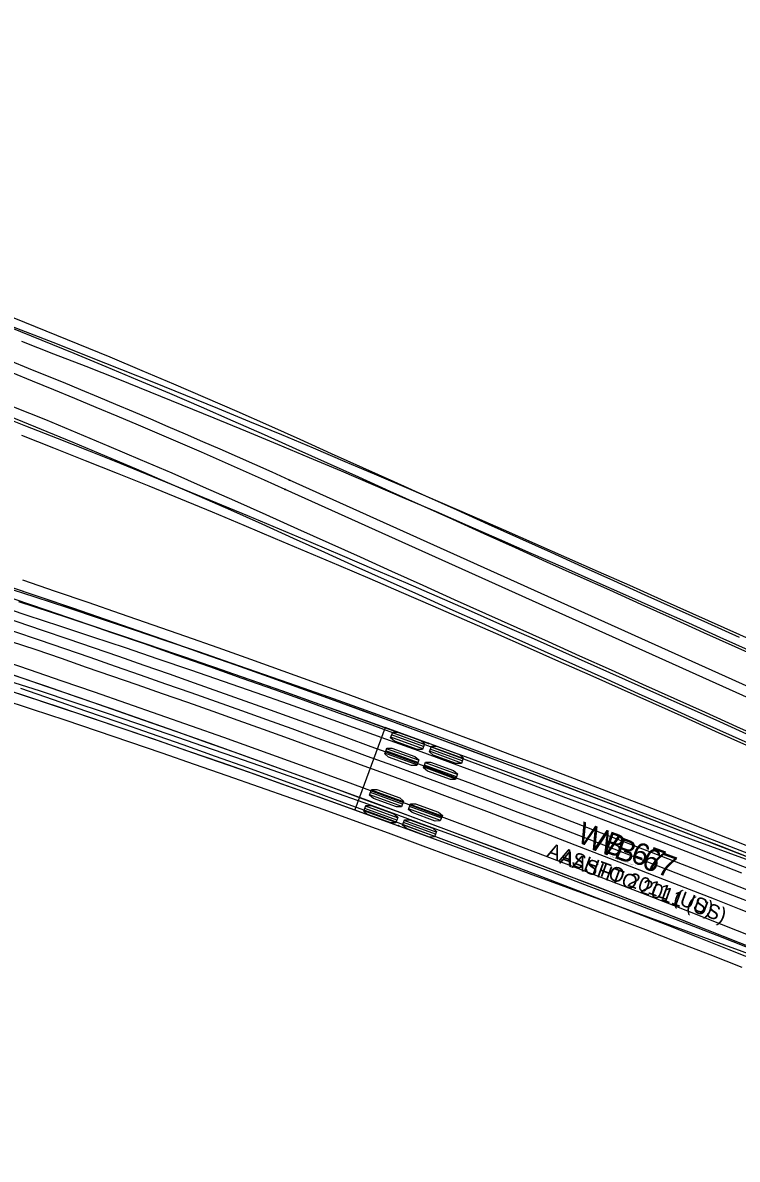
# Model space of a CAD drawing. Extents: x 916040 to 917457, y 328936 to 330267.
# Drawn here: x 916963.2 to 917032.5, y 329557.9 to 329668.1 of the extents above; entities that cross this region are included whole.
import ezdxf

# ---------------------------------------------------------------- set-up
doc = ezdxf.new("R2010")
doc.units = 0
for name, color, linetype in [('EB_Thru_WB67', 7, 'Continuous'), ('EB_Thru_WB67_v2', 7, 'Continuous'), ('NB_RightontoRoute25_WB67', 7, 'Continuous'), ('NB_ThruontoManchester_WB67', 7, 'Continuous'), ('SB_LeftontoRoute25_WB67', 7, 'Continuous'), ('WB_LeftontoSaco_WB67', 7, 'Continuous'), ('WB_RightontoManchester_WB67', 7, 'Continuous'), ('WB_Thru_WB67', 7, 'Continuous')]:
    doc.layers.add(name, color=color, linetype=linetype)

msp = doc.modelspace()

# ---------------------------------------------------------------- linework, layer by layer
at = {"layer": 'EB_Thru_WB67'}
for p, q in [((916998.31, 329599.77), (916995.39, 329591.79)), ((917048.09, 329581.6), (916998.31, 329599.77)), ((917002.13, 329598.14), (916999.03, 329599.27)), ((917001.97, 329597.71), (916998.87, 329598.84)), ((917002.05, 329597.92), (916998.95, 329599.05)), ((917001.4, 329596.16), (916998.3, 329597.29)), ((917001.48, 329596.37), (916998.38, 329597.5)), ((917001.56, 329596.59), (916998.46, 329597.72)), ((917005.73, 329596.33), (917002.63, 329597.47)), ((917005.8, 329596.55), (917002.7, 329597.68)), ((917005.88, 329596.76), (917002.78, 329597.9)), ((917005.16, 329594.78), (917002.06, 329595.92)), ((917005.24, 329595), (917002.14, 329596.13)), ((917005.32, 329595.21), (917002.22, 329596.35)), ((916999.93, 329592.13), (916996.83, 329593.26)), ((917000.01, 329592.35), (916996.91, 329593.48)), ((917000.09, 329592.56), (916996.99, 329593.69)), ((916995.39, 329591.79), (917045.18, 329573.62)), ((916999.37, 329590.58), (916996.27, 329591.71)), ((916999.45, 329590.8), (916996.35, 329591.93)), ((916999.53, 329591.01), (916996.43, 329592.14)), ((917003.69, 329590.76), (917000.59, 329591.89)), ((917003.77, 329590.98), (917000.67, 329592.11)), ((917003.85, 329591.19), (917000.75, 329592.32)), ((917003.2, 329589.43), (917000.1, 329590.56)), ((917003.28, 329589.64), (917000.18, 329590.77)), ((917003.13, 329589.21), (917000.03, 329590.34))]:
    msp.add_line(p, q, dxfattribs=at)
for points in [[(916961.68, 329613.51), (916964.85, 329612.44), (916968.01, 329611.36), (916971.18, 329610.27), (916974.34, 329609.17), (916977.5, 329608.07), (916980.66, 329606.96), (916983.82, 329605.84), (916986.97, 329604.72), (916990.12, 329603.59), (916993.27, 329602.45), (916996.42, 329601.31), (916999.56, 329600.15), (917002.7, 329599), (917005.84, 329597.83), (917008.97, 329596.66), (917012.11, 329595.48), (917015.24, 329594.29), (917018.36, 329593.1), (917021.49, 329591.9), (917024.61, 329590.69), (917027.73, 329589.48), (917030.85, 329588.26), (917033.96, 329587.03)], [(916963, 329611.92), (916966.18, 329610.88), (916969.36, 329609.83), (916972.53, 329608.76), (916975.7, 329607.69), (916978.87, 329606.61), (916982.03, 329605.52), (916985.2, 329604.42), (916988.36, 329603.31), (916991.51, 329602.2), (916994.66, 329601.08), (916997.81, 329599.94), (917000.96, 329598.8), (917002.53, 329598.23)], [(916962.36, 329604.83), (916965.51, 329603.76), (916968.65, 329602.68), (916971.8, 329601.59), (916974.94, 329600.49), (916978.08, 329599.39), (916981.22, 329598.27), (916984.36, 329597.16), (916987.49, 329596.03), (916990.62, 329594.9), (916993.75, 329593.76), (916996.88, 329592.62), (917000, 329591.46), (917003.12, 329590.31), (917006.24, 329589.14), (917009.36, 329587.97), (917012.47, 329586.79), (917015.58, 329585.6), (917018.69, 329584.41), (917021.79, 329583.2), (917024.9, 329582), (917028, 329580.78), (917031.09, 329579.56), (917034.19, 329578.33)], [(916960.36, 329603.84), (916963.52, 329602.81), (916966.67, 329601.76), (916969.82, 329600.71), (916972.97, 329599.64), (916976.11, 329598.57), (916979.26, 329597.49), (916982.4, 329596.4), (916985.53, 329595.3), (916988.67, 329594.19), (916991.8, 329593.07), (916994.93, 329591.95), (916998.06, 329590.82), (916999.62, 329590.25)]]:
    msp.add_lwpolyline(points, dxfattribs=at)
for points in [[(917002.14, 329598.19), (917001.95, 329597.65), (917001.46, 329597.65), (916999.22, 329598.46), (916998.85, 329598.78), (916999.05, 329599.32), (916999.54, 329599.32), (917001.77, 329598.51)], [(917001.58, 329596.64), (917001.38, 329596.1), (917000.89, 329596.1), (916998.66, 329596.91), (916998.28, 329597.23), (916998.48, 329597.77), (916998.97, 329597.77), (917001.2, 329596.96)], [(917005.9, 329596.82), (917005.71, 329596.28), (917005.21, 329596.28), (917002.98, 329597.09), (917002.61, 329597.41), (917002.8, 329597.95), (917003.3, 329597.95), (917005.53, 329597.14)], [(917005.34, 329595.27), (917005.14, 329594.73), (917004.65, 329594.73), (917002.42, 329595.54), (917002.04, 329595.86), (917002.24, 329596.4), (917002.73, 329596.4), (917004.96, 329595.59)], [(917000.11, 329592.62), (916999.91, 329592.08), (916999.42, 329592.07), (916997.19, 329592.89), (916996.81, 329593.21), (916997.01, 329593.75), (916997.5, 329593.75), (916999.74, 329592.94)], [(916999.54, 329591.07), (916999.35, 329590.53), (916998.86, 329590.52), (916996.62, 329591.34), (916996.25, 329591.66), (916996.44, 329592.2), (916996.94, 329592.2), (916999.17, 329591.39)], [(917003.87, 329591.24), (917003.67, 329590.71), (917003.18, 329590.7), (917000.95, 329591.52), (917000.57, 329591.84), (917000.77, 329592.38), (917001.26, 329592.38), (917003.49, 329591.56)], [(917003.3, 329589.69), (917003.11, 329589.16), (917002.61, 329589.15), (917000.38, 329589.97), (917000.01, 329590.29), (917000.2, 329590.83), (917000.7, 329590.83), (917002.93, 329590.01)]]:
    msp.add_lwpolyline(points, close=True, dxfattribs=at)
for centre in [(917002.53, 329598.23), (916999.62, 329590.25)]:
    msp.add_circle(centre, 0.0417, dxfattribs=at)
msp.add_arc((916478.21, 328181.95), 1507, 67.21233, 73.53304, dxfattribs=at)
at = {"layer": 'EB_Thru_WB67_v2'}
for p, q in [((916998.31, 329599.77), (916995.39, 329591.79)), ((917048.09, 329581.6), (916998.31, 329599.77)), ((917002.13, 329598.14), (916999.03, 329599.27)), ((917001.97, 329597.71), (916998.87, 329598.84)), ((917002.05, 329597.92), (916998.95, 329599.05)), ((917001.4, 329596.16), (916998.3, 329597.29)), ((917001.48, 329596.37), (916998.38, 329597.5)), ((917001.56, 329596.59), (916998.46, 329597.72)), ((917005.73, 329596.33), (917002.63, 329597.47)), ((917005.8, 329596.55), (917002.7, 329597.68)), ((917005.88, 329596.76), (917002.78, 329597.9)), ((917005.16, 329594.78), (917002.06, 329595.92)), ((917005.24, 329595), (917002.14, 329596.13)), ((917005.32, 329595.21), (917002.22, 329596.35)), ((916999.93, 329592.13), (916996.83, 329593.26)), ((917000.01, 329592.35), (916996.91, 329593.48)), ((917000.09, 329592.56), (916996.99, 329593.69)), ((916995.39, 329591.79), (917045.18, 329573.62)), ((916999.37, 329590.58), (916996.27, 329591.71)), ((916999.45, 329590.8), (916996.35, 329591.93)), ((916999.53, 329591.01), (916996.43, 329592.14)), ((917003.69, 329590.76), (917000.59, 329591.89)), ((917003.77, 329590.98), (917000.67, 329592.11)), ((917003.85, 329591.19), (917000.75, 329592.32)), ((917003.2, 329589.43), (917000.1, 329590.56)), ((917003.28, 329589.64), (917000.18, 329590.77)), ((917003.13, 329589.21), (917000.03, 329590.34))]:
    msp.add_line(p, q, dxfattribs=at)
for points in [[(916961.57, 329613.55), (916964.73, 329612.48), (916967.89, 329611.4), (916971.05, 329610.31), (916974.21, 329609.22), (916977.36, 329608.12), (916980.52, 329607.01), (916983.67, 329605.9), (916986.81, 329604.77), (916989.96, 329603.65), (916993.1, 329602.51), (916996.24, 329601.37), (916999.38, 329600.22), (917002.51, 329599.07), (917005.64, 329597.9), (917008.77, 329596.73), (917011.9, 329595.56), (917015.02, 329594.37), (917018.14, 329593.18), (917021.26, 329591.99), (917024.38, 329590.78), (917027.49, 329589.57), (917030.6, 329588.35), (917033.71, 329587.13)], [(916962.76, 329612), (916965.93, 329610.96), (916969.11, 329609.91), (916972.27, 329608.85), (916975.44, 329607.78), (916978.6, 329606.7), (916981.76, 329605.62), (916984.92, 329604.52), (916988.07, 329603.42), (916991.22, 329602.3), (916994.37, 329601.18), (916997.51, 329600.05), (917000.65, 329598.92), (917002.53, 329598.23)], [(916962.24, 329604.87), (916965.39, 329603.8), (916968.53, 329602.72), (916971.67, 329601.63), (916974.8, 329600.54), (916977.94, 329599.44), (916981.07, 329598.33), (916984.2, 329597.21), (916987.33, 329596.09), (916990.45, 329594.96), (916993.57, 329593.83), (916996.69, 329592.68), (916999.81, 329591.53), (917002.93, 329590.38), (917006.04, 329589.21), (917009.15, 329588.04), (917012.26, 329586.87), (917015.36, 329585.68), (917018.46, 329584.49), (917021.56, 329583.29), (917024.66, 329582.09), (917027.75, 329580.88), (917030.84, 329579.66), (917033.93, 329578.43)], [(916960.12, 329603.92), (916963.27, 329602.89), (916966.42, 329601.84), (916969.57, 329600.79), (916972.71, 329599.73), (916975.85, 329598.66), (916978.98, 329597.58), (916982.12, 329596.49), (916985.25, 329595.4), (916988.38, 329594.29), (916991.5, 329593.18), (916994.63, 329592.06), (916997.75, 329590.93), (916999.62, 329590.25)]]:
    msp.add_lwpolyline(points, dxfattribs=at)
for points in [[(917002.14, 329598.19), (917001.95, 329597.65), (917001.46, 329597.65), (916999.22, 329598.46), (916998.85, 329598.78), (916999.05, 329599.32), (916999.54, 329599.32), (917001.77, 329598.51)], [(917001.58, 329596.64), (917001.38, 329596.1), (917000.89, 329596.1), (916998.66, 329596.91), (916998.28, 329597.23), (916998.48, 329597.77), (916998.97, 329597.77), (917001.2, 329596.96)], [(917005.9, 329596.82), (917005.71, 329596.28), (917005.21, 329596.28), (917002.98, 329597.09), (917002.61, 329597.41), (917002.8, 329597.95), (917003.3, 329597.95), (917005.53, 329597.14)], [(917005.34, 329595.27), (917005.14, 329594.73), (917004.65, 329594.73), (917002.42, 329595.54), (917002.04, 329595.86), (917002.24, 329596.4), (917002.73, 329596.4), (917004.96, 329595.59)], [(917000.11, 329592.62), (916999.91, 329592.08), (916999.42, 329592.07), (916997.19, 329592.89), (916996.81, 329593.21), (916997.01, 329593.75), (916997.5, 329593.75), (916999.74, 329592.94)], [(916999.54, 329591.07), (916999.35, 329590.53), (916998.86, 329590.52), (916996.62, 329591.34), (916996.25, 329591.66), (916996.44, 329592.2), (916996.94, 329592.2), (916999.17, 329591.39)], [(917003.87, 329591.24), (917003.67, 329590.71), (917003.18, 329590.7), (917000.95, 329591.52), (917000.57, 329591.84), (917000.77, 329592.38), (917001.26, 329592.38), (917003.49, 329591.56)], [(917003.3, 329589.69), (917003.11, 329589.16), (917002.61, 329589.15), (917000.38, 329589.97), (917000.01, 329590.29), (917000.2, 329590.83), (917000.7, 329590.83), (917002.93, 329590.01)]]:
    msp.add_lwpolyline(points, close=True, dxfattribs=at)
for centre in [(917002.53, 329598.23), (916999.62, 329590.25)]:
    msp.add_circle(centre, 0.0417, dxfattribs=at)
msp.add_arc((916478.21, 328181.95), 1507, 67.21233, 73.53304, dxfattribs=at)
at = {"layer": 'NB_RightontoRoute25_WB67'}
for points in [[(916963.15, 329614.07), (916966.32, 329612.99), (916969.48, 329611.91), (916972.64, 329610.82), (916975.8, 329609.72), (916978.96, 329608.62), (916982.11, 329607.51), (916985.26, 329606.39), (916988.41, 329605.27), (916991.55, 329604.13), (916994.7, 329603), (916997.84, 329601.85), (917000.98, 329600.7), (917004.11, 329599.54), (917007.24, 329598.37), (917010.37, 329597.2), (917013.5, 329596.02), (917016.63, 329594.83), (917019.75, 329593.64), (917022.87, 329592.44), (917025.99, 329591.23), (917029.1, 329590.02), (917032.21, 329588.79), (917035.32, 329587.57)], [(916961.17, 329613.46), (916964.35, 329612.43), (916967.53, 329611.39), (916970.7, 329610.34), (916973.88, 329609.28), (916977.04, 329608.21), (916980.21, 329607.13), (916983.37, 329606.05), (916986.53, 329604.95), (916989.68, 329603.85), (916992.84, 329602.73), (916995.99, 329601.61), (916999.13, 329600.48), (917002.27, 329599.34), (917005.42, 329598.2), (917008.55, 329597.04), (917011.69, 329595.88), (917014.82, 329594.71), (917017.95, 329593.53), (917021.08, 329592.35), (917024.2, 329591.16), (917027.32, 329589.96), (917030.44, 329588.76), (917033.55, 329587.55)], [(916960.68, 329606.46), (916963.82, 329605.39), (916966.97, 329604.31), (916970.11, 329603.23), (916973.25, 329602.14), (916976.39, 329601.04), (916979.52, 329599.94), (916982.66, 329598.83), (916985.79, 329597.71), (916988.92, 329596.58), (916992.04, 329595.45), (916995.17, 329594.31), (916998.29, 329593.16), (917001.41, 329592.01), (917004.52, 329590.85), (917007.63, 329589.68), (917010.75, 329588.51), (917013.85, 329587.33), (917016.96, 329586.14), (917020.06, 329584.95), (917023.16, 329583.75), (917026.26, 329582.54), (917029.35, 329581.32), (917032.45, 329580.1), (917035.54, 329578.87)], [(916961.72, 329604.34), (916964.88, 329603.31), (916968.03, 329602.27), (916971.17, 329601.22), (916974.32, 329600.16), (916977.46, 329599.09), (916980.6, 329598.01), (916983.73, 329596.92), (916986.87, 329595.83), (916990, 329594.72), (916993.12, 329593.61), (916996.25, 329592.49), (916999.37, 329591.36), (917002.49, 329590.22), (917005.61, 329589.07), (917008.72, 329587.91), (917011.84, 329586.75), (917014.95, 329585.58), (917018.06, 329584.4), (917021.16, 329583.22), (917024.27, 329582.03), (917027.37, 329580.83), (917030.47, 329579.63), (917033.57, 329578.42)]]:
    msp.add_lwpolyline(points, dxfattribs=at)
msp.add_arc((916478.21, 328181.95), 1508, 67.21233, 73.53304, dxfattribs=at)
at = {"layer": 'NB_ThruontoManchester_WB67'}
msp.add_arc((916478.21, 328181.95), 1508, 67.21233, 73.53304, dxfattribs=at)
at = {"layer": 'SB_LeftontoRoute25_WB67'}
for points in [[(916960.41, 329611.71), (916963.59, 329610.67), (916966.76, 329609.63), (916969.94, 329608.57), (916973.11, 329607.51), (916976.28, 329606.43), (916979.44, 329605.35), (916982.61, 329604.26), (916985.77, 329603.16), (916988.92, 329602.05), (916992.07, 329600.93), (916995.22, 329599.81), (916998.37, 329598.68), (917001.52, 329597.53), (917004.66, 329596.38), (917007.81, 329595.22), (917010.95, 329594.05), (917014.09, 329592.88), (917017.23, 329591.7), (917020.37, 329590.51), (917023.5, 329589.31), (917026.63, 329588.11), (917029.75, 329586.9), (917032.88, 329585.68)], [(916962.31, 329612.24), (916965.47, 329611.17), (916968.64, 329610.08), (916971.8, 329608.99), (916974.96, 329607.9), (916978.12, 329606.79), (916981.28, 329605.68), (916984.43, 329604.56), (916987.58, 329603.44), (916990.73, 329602.31), (916993.87, 329601.17), (916997.02, 329600.02), (917000.16, 329598.87), (917003.29, 329597.71), (917006.43, 329596.54), (917009.56, 329595.37), (917012.69, 329594.19), (917015.82, 329593), (917018.94, 329591.81), (917022.07, 329590.6), (917025.18, 329589.4), (917028.3, 329588.18), (917031.41, 329586.96), (917034.53, 329585.73)], [(916960.94, 329602.59), (916964.1, 329601.56), (916967.25, 329600.51), (916970.4, 329599.45), (916973.54, 329598.39), (916976.68, 329597.31), (916979.82, 329596.23), (916982.96, 329595.13), (916986.1, 329594.03), (916989.23, 329592.92), (916992.36, 329591.81), (916995.48, 329590.68), (916998.61, 329589.55), (917001.73, 329588.4), (917004.86, 329587.25), (917007.98, 329586.09), (917011.11, 329584.92), (917014.22, 329583.75), (917017.34, 329582.56), (917020.46, 329581.37), (917023.57, 329580.18), (917026.68, 329578.97), (917029.79, 329577.76), (917032.9, 329576.55)], [(916962.98, 329603.57), (916966.13, 329602.49), (916969.27, 329601.4), (916972.41, 329600.31), (916975.55, 329599.22), (916978.69, 329598.11), (916981.83, 329597), (916984.96, 329595.88), (916988.09, 329594.75), (916991.22, 329593.62), (916994.35, 329592.48), (916997.47, 329591.33), (917000.59, 329590.18), (917003.71, 329589.02), (917006.82, 329587.85), (917009.94, 329586.68), (917013.05, 329585.5), (917016.15, 329584.31), (917019.26, 329583.11), (917022.36, 329581.91), (917025.46, 329580.7), (917028.56, 329579.49), (917031.65, 329578.26), (917034.75, 329577.03)]]:
    msp.add_lwpolyline(points, dxfattribs=at)
msp.add_arc((916478.21, 328181.95), 1506, 67.21233, 73.53304, dxfattribs=at)
at = {"layer": 'WB_LeftontoSaco_WB67'}
msp.add_line((917137.05, 329556.02), (916988.64, 329622.84), dxfattribs=at)
for points in [[(917035.29, 329606.22), (917032.25, 329607.59), (917029.21, 329608.96), (917026.17, 329610.33), (917023.13, 329611.7), (917020.09, 329613.07), (917017.05, 329614.44), (917014.01, 329615.81), (917010.97, 329617.18), (917007.92, 329618.55), (917004.88, 329619.92), (917001.84, 329621.29), (916998.8, 329622.66), (916995.76, 329624.02), (916992.72, 329625.39), (916989.68, 329626.76), (916986.63, 329628.13), (916983.57, 329629.47), (916980.5, 329630.81), (916977.43, 329632.13), (916974.34, 329633.44), (916971.26, 329634.73), (916968.16, 329636.01), (916965.06, 329637.28), (916961.95, 329638.53)], [(917033.84, 329607.15), (917030.79, 329608.51), (917027.75, 329609.88), (917024.7, 329611.24), (917021.65, 329612.6), (917018.6, 329613.95), (917015.54, 329615.31), (917012.48, 329616.65), (917009.42, 329617.99), (917006.36, 329619.33), (917003.3, 329620.66), (917000.23, 329621.98), (916997.15, 329623.3), (916994.08, 329624.61), (916991, 329625.91), (916987.91, 329627.2), (916984.82, 329628.48), (916981.73, 329629.75), (916978.64, 329631.02), (916975.54, 329632.27), (916972.43, 329633.52), (916969.32, 329634.75), (916966.21, 329635.97), (916963.09, 329637.19)], [(917035.05, 329597.56), (917032.01, 329598.93), (917028.97, 329600.3), (917025.93, 329601.67), (917022.89, 329603.04), (917019.84, 329604.41), (917016.8, 329605.78), (917013.76, 329607.14), (917010.72, 329608.51), (917007.68, 329609.88), (917004.64, 329611.25), (917001.6, 329612.62), (916998.56, 329613.99), (916995.52, 329615.36), (916992.48, 329616.73), (916989.43, 329618.1), (916986.39, 329619.47), (916983.35, 329620.83), (916980.31, 329622.17), (916977.26, 329623.5), (916974.21, 329624.81), (916971.15, 329626.11), (916968.08, 329627.39), (916965.01, 329628.66), (916961.94, 329629.91)], [(917033.4, 329598.03), (917030.36, 329599.39), (917027.32, 329600.76), (917024.28, 329602.12), (917021.23, 329603.48), (917018.19, 329604.83), (917015.15, 329606.18), (917012.11, 329607.53), (917009.06, 329608.87), (917006.02, 329610.21), (917002.97, 329611.54), (916999.92, 329612.86), (916996.87, 329614.17), (916993.82, 329615.48), (916990.76, 329616.78), (916987.7, 329618.07), (916984.64, 329619.35), (916981.57, 329620.63), (916978.51, 329621.89), (916975.43, 329623.15), (916972.36, 329624.39), (916969.28, 329625.62), (916966.2, 329626.85), (916963.11, 329628.06)]]:
    msp.add_lwpolyline(points, dxfattribs=at)
msp.add_circle((916988.64, 329622.84), 0.0417, dxfattribs=at)
msp.add_circle((916988.64, 329622.84), 0.0417, dxfattribs=at)
msp.add_arc((916692.61, 328965.42), 721, 65.75845, 77.04963, dxfattribs=at)
at = {"layer": 'WB_RightontoManchester_WB67'}
msp.add_line((917137.46, 329556.93), (916989.05, 329623.75), dxfattribs=at)
for points in [[(917034.24, 329608.06), (917031.19, 329609.43), (917028.14, 329610.8), (917025.1, 329612.16), (917022.04, 329613.52), (917018.99, 329614.87), (917015.93, 329616.23), (917012.87, 329617.57), (917009.81, 329618.92), (917006.75, 329620.25), (917003.68, 329621.58), (917000.61, 329622.91), (916997.53, 329624.22), (916994.46, 329625.53), (916991.37, 329626.83), (916988.29, 329628.13), (916985.2, 329629.41), (916982.1, 329630.68), (916979.01, 329631.95), (916975.9, 329633.2), (916972.8, 329634.45), (916969.69, 329635.68), (916966.57, 329636.91), (916963.45, 329638.12), (916960.33, 329639.32)], [(917032.66, 329608.5), (917029.62, 329609.87), (917026.58, 329611.24), (917023.54, 329612.61), (917020.5, 329613.98), (917017.46, 329615.35), (917014.42, 329616.72), (917011.38, 329618.09), (917008.33, 329619.46), (917005.29, 329620.83), (917002.25, 329622.2), (916999.21, 329623.57), (916996.17, 329624.94), (916993.13, 329626.31), (916990.09, 329627.68), (916987.03, 329629.04), (916983.97, 329630.39), (916980.91, 329631.72), (916977.83, 329633.05), (916974.75, 329634.35), (916971.66, 329635.65), (916968.56, 329636.93), (916965.46, 329638.2), (916962.35, 329639.45)], [(917033.8, 329598.94), (917030.76, 329600.31), (917027.72, 329601.67), (917024.67, 329603.04), (917021.63, 329604.4), (917018.59, 329605.75), (917015.54, 329607.1), (917012.5, 329608.45), (917009.45, 329609.79), (917006.41, 329611.13), (917003.36, 329612.46), (917000.31, 329613.78), (916997.25, 329615.1), (916994.2, 329616.41), (916991.14, 329617.71), (916988.08, 329619), (916985.01, 329620.28), (916981.95, 329621.55), (916978.88, 329622.82), (916975.8, 329624.07), (916972.73, 329625.32), (916969.65, 329626.55), (916966.56, 329627.78), (916963.48, 329628.99), (916960.39, 329630.19)], [(917035.46, 329598.47), (917032.42, 329599.84), (917029.38, 329601.21), (917026.34, 329602.58), (917023.3, 329603.95), (917020.26, 329605.32), (917017.21, 329606.69), (917014.17, 329608.06), (917011.13, 329609.43), (917008.09, 329610.8), (917005.05, 329612.16), (917002.01, 329613.53), (916998.97, 329614.9), (916995.93, 329616.27), (916992.89, 329617.64), (916989.85, 329619.01), (916986.8, 329620.38), (916983.76, 329621.74), (916980.72, 329623.08), (916977.66, 329624.41), (916974.61, 329625.72), (916971.55, 329627.02), (916968.48, 329628.31), (916965.41, 329629.58), (916962.33, 329630.83)]]:
    msp.add_lwpolyline(points, dxfattribs=at)
msp.add_circle((916989.05, 329623.75), 0.0417, dxfattribs=at)
msp.add_circle((916989.05, 329623.75), 0.0417, dxfattribs=at)
msp.add_arc((916692.61, 328965.42), 722, 65.75845, 75.08052, dxfattribs=at)
at = {"layer": 'WB_Thru_WB67'}
msp.add_line((917137.05, 329556.02), (916988.64, 329622.84), dxfattribs=at)
for points in [[(917035.29, 329606.22), (917032.25, 329607.59), (917029.21, 329608.96), (917026.17, 329610.33), (917023.13, 329611.7), (917020.09, 329613.07), (917017.05, 329614.44), (917014.01, 329615.81), (917010.97, 329617.18), (917007.92, 329618.55), (917004.88, 329619.92), (917001.84, 329621.29), (916998.8, 329622.66), (916995.76, 329624.02), (916992.72, 329625.39), (916989.68, 329626.76), (916986.63, 329628.13), (916983.57, 329629.47), (916980.5, 329630.81), (916977.43, 329632.13), (916974.34, 329633.44), (916971.26, 329634.73), (916968.16, 329636.01), (916965.06, 329637.28), (916961.95, 329638.53)], [(917033.84, 329607.15), (917030.79, 329608.51), (917027.75, 329609.88), (917024.7, 329611.24), (917021.65, 329612.6), (917018.6, 329613.95), (917015.54, 329615.31), (917012.48, 329616.65), (917009.42, 329617.99), (917006.36, 329619.33), (917003.3, 329620.66), (917000.23, 329621.98), (916997.15, 329623.3), (916994.08, 329624.61), (916991, 329625.91), (916987.91, 329627.2), (916984.82, 329628.48), (916981.73, 329629.75), (916978.64, 329631.02), (916975.54, 329632.27), (916972.43, 329633.52), (916969.32, 329634.75), (916966.21, 329635.97), (916963.09, 329637.19)], [(917035.05, 329597.56), (917032.01, 329598.93), (917028.97, 329600.3), (917025.93, 329601.67), (917022.89, 329603.04), (917019.84, 329604.41), (917016.8, 329605.78), (917013.76, 329607.14), (917010.72, 329608.51), (917007.68, 329609.88), (917004.64, 329611.25), (917001.6, 329612.62), (916998.56, 329613.99), (916995.52, 329615.36), (916992.48, 329616.73), (916989.43, 329618.1), (916986.39, 329619.47), (916983.35, 329620.83), (916980.31, 329622.17), (916977.26, 329623.5), (916974.21, 329624.81), (916971.15, 329626.11), (916968.08, 329627.39), (916965.01, 329628.66), (916961.94, 329629.91)], [(917033.4, 329598.03), (917030.36, 329599.39), (917027.32, 329600.76), (917024.28, 329602.12), (917021.23, 329603.48), (917018.19, 329604.83), (917015.15, 329606.18), (917012.11, 329607.53), (917009.06, 329608.87), (917006.02, 329610.21), (917002.97, 329611.54), (916999.92, 329612.86), (916996.87, 329614.17), (916993.82, 329615.48), (916990.76, 329616.78), (916987.7, 329618.07), (916984.64, 329619.35), (916981.57, 329620.63), (916978.51, 329621.89), (916975.43, 329623.15), (916972.36, 329624.39), (916969.28, 329625.62), (916966.2, 329626.85), (916963.11, 329628.06)]]:
    msp.add_lwpolyline(points, dxfattribs=at)
msp.add_circle((916988.64, 329622.84), 0.0417, dxfattribs=at)
msp.add_circle((916988.64, 329622.84), 0.0417, dxfattribs=at)
msp.add_arc((916692.61, 328965.42), 721, 65.75845, 77.04963, dxfattribs=at)

# ---------------------------------------------------------------- texts
at = {"layer": 'EB_Thru_WB67'}
for s, height, p in [('WB-67', 2.125, (917017.89, 329588.1)), ('AASHTO 2011 (US)', 1.4167, (917015.17, 329586.64))]:
    msp.add_text(s, height=height, rotation=339.9476, dxfattribs=at).set_placement(p)
at = {"layer": 'EB_Thru_WB67_v2'}
for s, height, p in [('WB-67', 2.125, (917016.81, 329588.68)), ('AASHTO 2011 (US)', 1.4167, (917013.91, 329587.29)), ('(c) 2016 Transoft Solutions, Inc. All rights reserved.', 0.085, (917020.1, 329587.25))]:
    msp.add_text(s, height=height, rotation=339.9477, dxfattribs=at).set_placement(p)

doc.saveas('drawing.dxf')
